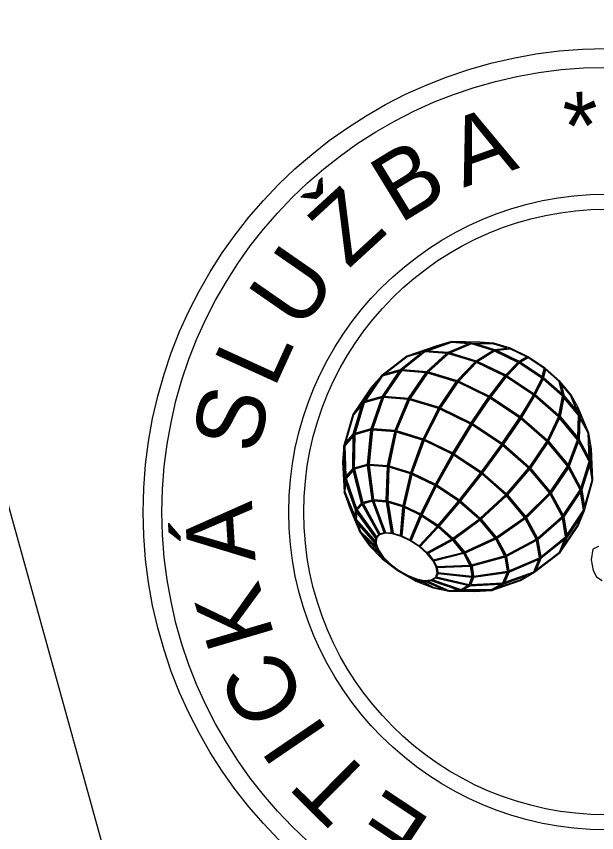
# Model space of a CAD drawing. Extents: x -821172 to -820632, y -1070921 to -1069931.
# Drawn here: x -820939.57 to -820934.74, y -1069983.01 to -1069976.22 of the extents above; entities that cross this region are included whole.
import ezdxf

# ---------------------------------------------------------------- set-up
doc = ezdxf.new("R2010")
doc.units = 0
doc.layers.add('Popisove_pole', color=7, linetype='Continuous')

msp = doc.modelspace()

# ---------------------------------------------------------------- linework, layer by layer
at = {"layer": 'Popisove_pole'}
for p, q in [((-820922.8738, -1070040.6021), (-820945.6304, -1069958.705)), ((-820936.0656, -1069978.9676), (-820936.3151, -1069979.0542)), ((-820936.5533, -1069980.6588), (-820936.7069, -1069980.5118)), ((-820936.5134, -1069980.717), (-820936.6302, -1069980.6233)), ((-820936.4561, -1069980.7752), (-820936.5203, -1069980.7351)), ((-820936.3865, -1069980.8284), (-820936.3868, -1069980.8372)), ((-820936.3109, -1069980.8718), (-820936.2417, -1069980.9205)), ((-820936.2359, -1069980.9016), (-820936.0978, -1069980.9776)), ((-820936.1683, -1069980.915), (-820935.968, -1069981.0034))]:
    msp.add_line(p, q, dxfattribs=at)
for points in [[(-820936.2417, -1069980.9205), (-820936.0978, -1069980.9776), (-820935.968, -1069981.0034), (-820935.755, -1069981.008), (-820935.6092, -1069980.9972), (-820935.371, -1069980.9153), (-820935.2541, -1069980.847), (-820935.0412, -1069980.6823), (-820934.8907, -1069980.4598), (-820934.8386, -1069980.3319), (-820934.7669, -1069980.0799), (-820934.7797, -1069979.8188), (-820934.8007, -1069979.6889), (-820934.8911, -1069979.4769), (-820934.9483, -1069979.3692), (-820935.0427, -1069979.2562), (-820935.1658, -1069979.1481), (-820935.3066, -1069979.0544), (-820935.4528, -1069978.9834), (-820935.5912, -1069978.9414), (-820935.7096, -1069978.9323), (-820935.9449, -1069978.9276), (-820936.0677, -1069978.9617), (-820936.3171, -1069979.0483), (-820936.5256, -1069979.2094), (-820936.6162, -1069979.3116), (-820936.7667, -1069979.5342), (-820936.8398, -1069979.7919), (-820936.8512, -1069979.9303), (-820936.839, -1069980.1789), (-820936.7879, -1069980.3207), (-820936.7069, -1069980.5118), (-820936.6302, -1069980.6233), (-820936.5203, -1069980.7351), (-820936.3868, -1069980.8372)], [(-820935.944, -1069978.9339), (-820936.1395, -1069979.0033), (-820935.9711, -1069979.0163), (-820935.8051, -1069978.9447)], [(-820935.779, -1069978.9471), (-820935.9519, -1069979.0216), (-820935.7381, -1069979.0864), (-820935.6009, -1069979.001)], [(-820935.5921, -1069978.9477), (-820935.7364, -1069978.9469), (-820935.5853, -1069978.9927), (-820935.4832, -1069978.9807)], [(-820935.5639, -1069979.0028), (-820935.3819, -1069979.0912), (-820935.3199, -1069979.0549), (-820935.4538, -1069978.9898)], [(-820936.4965, -1069979.1948), (-820936.3676, -1069979.159), (-820936.1968, -1069979.0213), (-820936.3143, -1069979.054)], [(-820936.1673, -1069979.0136), (-820936.3485, -1069979.1597), (-820936.1501, -1069979.175), (-820935.9852, -1069979.0278)], [(-820935.9685, -1069979.0297), (-820936.1354, -1069979.1787), (-820935.8964, -1069979.2512), (-820935.7487, -1069979.0963)], [(-820935.5855, -1069979.0062), (-820935.7243, -1069979.0926), (-820935.4927, -1069979.2051), (-820935.3921, -1069979.1002)], [(-820935.3068, -1069979.0617), (-820935.3698, -1069979.0986), (-820935.1887, -1069979.2191), (-820935.1728, -1069979.1509)], [(-820935.7358, -1069979.1008), (-820935.8841, -1069979.2564), (-820935.6288, -1069979.3804), (-820935.501, -1069979.2149)], [(-820935.3807, -1069979.1064), (-820935.4817, -1069979.2116), (-820935.2568, -1069979.3612), (-820935.1927, -1069979.2315)], [(-820936.6614, -1069979.4214), (-820936.5191, -1069979.3818), (-820936.3794, -1069979.1753), (-820936.5217, -1069979.2148)], [(-820936.504, -1069979.3818), (-820936.3016, -1069979.3975), (-820936.1591, -1069979.1869), (-820936.3615, -1069979.1712)], [(-820936.2885, -1069979.4005), (-820936.0476, -1069979.4735), (-820935.9044, -1069979.2618), (-820936.1453, -1069979.1888)], [(-820935.1621, -1069979.1597), (-820935.1778, -1069979.2271), (-820935.0234, -1069979.3627), (-820935.0483, -1069979.2596)], [(-820936.0358, -1069979.4784), (-820935.7796, -1069979.6028), (-820935.6362, -1069979.3907), (-820935.8924, -1069979.2663)], [(-820935.49, -1069979.2211), (-820935.6179, -1069979.3868), (-820935.371, -1069979.551), (-820935.2628, -1069979.3723)], [(-820935.1827, -1069979.2394), (-820935.2466, -1069979.3688), (-820935.0513, -1069979.5405), (-820935.0195, -1069979.3828)], [(-820936.7082, -1069979.4587), (-820936.681, -1069979.4281), (-820936.5841, -1069979.2849), (-820936.6113, -1069979.3155)], [(-820935.0303, -1069979.2808), (-820935.0069, -1069979.3776), (-820934.9011, -1069979.5042), (-820934.9538, -1069979.3724)], [(-820936.7472, -1069979.6889), (-820936.6135, -1069979.6517), (-820936.525, -1069979.3965), (-820936.6711, -1069979.437)], [(-820936.5109, -1069979.3938), (-820936.6001, -1069979.6512), (-820936.4135, -1069979.6657), (-820936.3075, -1069979.4096)], [(-820936.401, -1069979.6683), (-820936.1798, -1069979.7353), (-820936.0539, -1069979.4847), (-820936.2948, -1069979.4117)], [(-820935.7688, -1069979.6091), (-820935.5213, -1069979.7738), (-820935.3778, -1069979.5616), (-820935.6253, -1069979.3969)], [(-820935.2529, -1069979.38), (-820935.361, -1069979.5586), (-820935.1459, -1069979.7476), (-820935.0549, -1069979.5539)], [(-820935.0091, -1069979.3945), (-820935.0405, -1069979.5506), (-820934.8941, -1069979.7259), (-820934.8871, -1069979.5405)], [(-820936.8263, -1069979.7673), (-820936.7621, -1069979.6948), (-820936.6903, -1069979.4574), (-820936.7611, -1069979.5372)], [(-820934.8998, -1069979.4737), (-820934.8751, -1069979.5357), (-820934.8636, -1069979.5572), (-820934.8967, -1069979.4796)], [(-820936.1681, -1069979.74), (-820935.9331, -1069979.8542), (-820935.7864, -1069979.6134), (-820936.0422, -1069979.4891)], [(-820935.3679, -1069979.5692), (-820935.5113, -1069979.7813), (-820935.2955, -1069979.971), (-820935.152, -1069979.7589)], [(-820935.0458, -1069979.5638), (-820935.1364, -1069979.7569), (-820934.9731, -1069979.9523), (-820934.8956, -1069979.7436)], [(-820934.8754, -1069979.5618), (-820934.8822, -1069979.7409), (-820934.7994, -1069979.8966), (-820934.8069, -1069979.6906)], [(-820936.7539, -1069979.9775), (-820936.6433, -1069979.9468), (-820936.6158, -1069979.6653), (-820936.7503, -1069979.7027)], [(-820936.603, -1069979.6635), (-820936.6306, -1069979.9459), (-820936.4769, -1069979.9578), (-820936.417, -1069979.678)], [(-820936.4047, -1069979.6802), (-820936.4646, -1069979.9602), (-820936.2823, -1069980.0154), (-820936.1847, -1069979.7469)], [(-820935.7755, -1069979.6196), (-820935.9222, -1069979.8604), (-820935.6952, -1069980.0115), (-820935.5285, -1069979.784)], [(-820936.8239, -1069980.048), (-820936.7665, -1069979.9834), (-820936.763, -1069979.7146), (-820936.8335, -1069979.7941)], [(-820936.173, -1069979.7515), (-820936.2707, -1069980.02), (-820936.0768, -1069980.1141), (-820935.9393, -1069979.865)], [(-820935.5186, -1069979.7916), (-820935.6853, -1069980.0191), (-820935.4872, -1069980.1931), (-820935.303, -1069979.981)], [(-820935.1432, -1069979.7682), (-820935.2864, -1069979.98), (-820935.122, -1069980.1768), (-820934.9788, -1069979.965)], [(-820934.8875, -1069979.7576), (-820934.9642, -1069979.9641), (-820934.8677, -1069980.1456), (-820934.7989, -1069979.9242)], [(-820934.7908, -1069979.789), (-820934.786, -1069979.9229), (-820934.7786, -1069979.9684), (-820934.7859, -1069979.8194)], [(-820935.9285, -1069979.8713), (-820936.0659, -1069980.1203), (-820935.8786, -1069980.245), (-820935.7028, -1069980.0214)], [(-820936.8374, -1069980.0837), (-820936.8358, -1069980.0637), (-820936.8421, -1069979.896), (-820936.845, -1069979.9304)], [(-820934.7941, -1069979.9508), (-820934.8598, -1069980.1622), (-820934.8369, -1069980.3032), (-820934.7732, -1069980.0795)], [(-820936.7343, -1069980.3159), (-820936.694, -1069980.2705), (-820936.7634, -1069979.9987), (-820936.8224, -1069980.0652)], [(-820936.6827, -1069980.2645), (-820936.6062, -1069980.2432), (-820936.6427, -1069979.9596), (-820936.7527, -1069979.9902)], [(-820936.6303, -1069979.9585), (-820936.5937, -1069980.242), (-820936.4869, -1069980.2502), (-820936.4784, -1069979.9702)], [(-820936.4659, -1069979.9728), (-820936.4745, -1069980.2524), (-820936.3471, -1069980.291), (-820936.2859, -1069980.0274)], [(-820935.2943, -1069979.99), (-820935.4784, -1069980.202), (-820935.3274, -1069980.3827), (-820935.13, -1069980.1868)], [(-820934.9716, -1069979.9767), (-820935.1142, -1069980.1875), (-820935.016, -1069980.3722), (-820934.8735, -1069980.1614)], [(-820936.2741, -1069980.0322), (-820936.3353, -1069980.2955), (-820936.1992, -1069980.3616), (-820936.0826, -1069980.1252)], [(-820935.6929, -1069980.029), (-820935.8687, -1069980.2526), (-820935.7053, -1069980.3961), (-820935.4959, -1069980.2021)], [(-820936.7476, -1069980.384), (-820936.743, -1069980.3289), (-820936.8257, -1069980.0936), (-820936.8326, -1069980.1779)], [(-820936.0717, -1069980.1315), (-820936.1883, -1069980.3677), (-820936.0567, -1069980.4553), (-820935.8866, -1069980.2547)], [(-820935.4872, -1069980.211), (-820935.6966, -1069980.4051), (-820935.5722, -1069980.554), (-820935.337, -1069980.3907)], [(-820935.1231, -1069980.1975), (-820935.3202, -1069980.3931), (-820935.2297, -1069980.5633), (-820935.0245, -1069980.3829)], [(-820934.8698, -1069980.1783), (-820935.0101, -1069980.3858), (-820934.9855, -1069980.5379), (-820934.8452, -1069980.3304)], [(-820936.5683, -1069980.5531), (-820936.5506, -1069980.5331), (-820936.6884, -1069980.283), (-820936.7287, -1069980.3285)], [(-820936.6779, -1069980.2761), (-820936.5399, -1069980.5266), (-820936.5055, -1069980.5171), (-820936.6031, -1069980.2554)], [(-820936.59, -1069980.2548), (-820936.4928, -1069980.5153), (-820936.443, -1069980.5192), (-820936.4862, -1069980.2628)], [(-820936.473, -1069980.2659), (-820936.43, -1069980.5212), (-820936.369, -1069980.5397), (-820936.3491, -1069980.3034)], [(-820935.8766, -1069980.2623), (-820936.0467, -1069980.463), (-820935.9321, -1069980.5638), (-820935.7152, -1069980.4041)], [(-820936.737, -1069980.4082), (-820936.5774, -1069980.5907), (-820936.5753, -1069980.5649), (-820936.7319, -1069980.3456)], [(-820936.337, -1069980.3085), (-820936.3568, -1069980.5442), (-820936.2905, -1069980.5764), (-820936.2044, -1069980.3729)], [(-820936.1935, -1069980.3793), (-820936.2795, -1069980.5826), (-820936.2148, -1069980.6256), (-820936.0651, -1069980.4648)], [(-820935.7063, -1069980.413), (-820935.9234, -1069980.5729), (-820935.8363, -1069980.677), (-820935.5834, -1069980.5602)], [(-820935.3301, -1069980.4011), (-820935.5652, -1069980.5644), (-820935.4907, -1069980.7045), (-820935.24, -1069980.5706)], [(-820935.0211, -1069980.3965), (-820935.2248, -1069980.5756), (-820935.2018, -1069980.7179), (-820934.9959, -1069980.5518)], [(-820934.867, -1069980.3851), (-820934.9836, -1069980.5574), (-820935.0128, -1069980.6291), (-820934.8963, -1069980.4568)], [(-820936.5682, -1069980.6359), (-820936.5779, -1069980.6092), (-820936.7263, -1069980.4394), (-820936.7015, -1069980.5083)], [(-820936.2049, -1069980.6333), (-820936.1489, -1069980.6825), (-820935.9433, -1069980.5706), (-820936.055, -1069980.4723)], [(-820936.5425, -1069980.6856), (-820936.5581, -1069980.6629), (-820936.6673, -1069980.5583), (-820936.6256, -1069980.619)], [(-820936.1497, -1069980.6901), (-820936.2139, -1069980.6337), (-820936.2873, -1069980.5849), (-820936.3634, -1069980.5479), (-820936.4355, -1069980.526), (-820936.4972, -1069980.5213), (-820936.543, -1069980.534), (-820936.5688, -1069980.5631), (-820936.5724, -1069980.606), (-820936.5533, -1069980.6588), (-820936.5134, -1069980.717), (-820936.4561, -1069980.7752), (-820936.3865, -1069980.8284), (-820936.3109, -1069980.8718), (-820936.2359, -1069980.9016), (-820936.1683, -1069980.915), (-820936.1139, -1069980.911), (-820936.0777, -1069980.8899), (-820936.0629, -1069980.8535), (-820936.0707, -1069980.8051), (-820936.1006, -1069980.7489)], [(-820936.14, -1069980.6919), (-820936.0983, -1069980.742), (-820935.8493, -1069980.681), (-820935.9339, -1069980.5797)], [(-820935.8294, -1069980.6876), (-820935.7776, -1069980.7851), (-820935.5025, -1069980.709), (-820935.5761, -1069980.5706)], [(-820935.2363, -1069980.5828), (-820935.4864, -1069980.7164), (-820935.4674, -1069980.834), (-820935.2132, -1069980.7256)], [(-820935.0041, -1069980.5745), (-820935.201, -1069980.7333), (-820935.2395, -1069980.8278), (-820935.0464, -1069980.6784)], [(-820936.5164, -1069980.7302), (-820936.4976, -1069980.7419), (-820936.5176, -1069980.7216), (-820936.5518, -1069980.6942)], [(-820935.8413, -1069980.6919), (-820936.0913, -1069980.7531), (-820936.0671, -1069980.7987), (-820935.791, -1069980.7866)], [(-820935.4984, -1069980.7208), (-820935.7737, -1069980.7969), (-820935.7606, -1069980.8782), (-820935.4794, -1069980.8376)], [(-820935.2177, -1069980.7412), (-820935.4674, -1069980.8476), (-820935.501, -1069980.9298), (-820935.2588, -1069980.8421)], [(-820936.3871, -1069980.8291), (-820936.3927, -1069980.8249)], [(-820936.0634, -1069980.811), (-820936.0575, -1069980.8478), (-820935.7732, -1069980.8782), (-820935.7861, -1069980.7989)], [(-820936.3708, -1069980.8392), (-820936.3564, -1069980.8475)], [(-820936.1881, -1069980.9351), (-820936.2386, -1069980.9072), (-820936.2641, -1069980.8971), (-820936.2387, -1069980.915)], [(-820935.811, -1069980.9577), (-820936.0767, -1069980.8965), (-820936.0989, -1069980.9095), (-820935.8644, -1069980.9889)], [(-820935.7747, -1069980.8906), (-820936.0589, -1069980.8602), (-820936.0692, -1069980.8854), (-820935.798, -1069980.9479)], [(-820935.4822, -1069980.8506), (-820935.7613, -1069980.891), (-820935.7847, -1069980.9484), (-820935.5164, -1069980.9344)], [(-820935.3167, -1069980.8763), (-820935.5094, -1069980.9461), (-820935.5515, -1069980.9707), (-820935.3736, -1069980.9095)], [(-820936.0225, -1069980.9862), (-820936.1702, -1069980.921), (-820936.1975, -1069980.9156), (-820936.0957, -1069980.9717)], [(-820935.8949, -1069980.9918), (-820936.1147, -1069980.9174), (-820936.1428, -1069980.9194), (-820935.9669, -1069980.9971)], [(-820935.5374, -1069980.948), (-820935.7924, -1069980.9613), (-820935.8408, -1069980.9896), (-820935.6108, -1069980.9909)]]:
    msp.add_lwpolyline(points, close=True, dxfattribs=at)
for points in [[(-820936.4972, -1069980.5213), (-820936.5993, -1069980.2478), (-820936.6375, -1069979.9517), (-820936.6086, -1069979.6568), (-820936.5152, -1069979.3872), (-820936.3647, -1069979.1647), (-820936.1693, -1069979.0072), (-820935.9449, -1069978.9276)], [(-820934.8007, -1069979.6889), (-820934.8808, -1069979.5383), (-820935.0127, -1069979.3805), (-820935.1847, -1069979.2293), (-820935.3816, -1069979.0983), (-820935.5859, -1069978.9991), (-820935.7794, -1069978.9404), (-820935.9449, -1069978.9276)], [(-820936.4355, -1069980.526), (-820936.4809, -1069980.257), (-820936.4719, -1069979.9645), (-820936.4094, -1069979.6723), (-820936.2984, -1069979.404), (-820936.1479, -1069979.1815), (-820935.9701, -1069979.0227), (-820935.7794, -1069978.9404), (-820935.5912, -1069978.9414)], [(-820936.3634, -1069980.5479), (-820936.3425, -1069980.2989), (-820936.2785, -1069980.0231), (-820936.1766, -1069979.7428), (-820936.045, -1069979.4808), (-820935.8945, -1069979.2583), (-820935.7372, -1069979.0932), (-820935.5859, -1069978.9991), (-820935.4528, -1069978.9834)], [(-820934.7669, -1069980.0799), (-820934.7922, -1069979.9235), (-820934.8885, -1069979.7423), (-820935.0473, -1069979.5523), (-820935.2543, -1069979.3704), (-820935.4913, -1069979.2127), (-820935.7372, -1069979.0932), (-820935.9701, -1069979.0227), (-820936.1693, -1069979.0072), (-820936.3171, -1069979.0483)], [(-820936.2873, -1069980.5849), (-820936.1963, -1069980.3699), (-820936.0742, -1069980.1223), (-820935.9307, -1069979.8623), (-820935.7775, -1069979.6108), (-820935.627, -1069979.3883), (-820935.4913, -1069979.2127), (-820935.3816, -1069979.0983), (-820935.3066, -1069979.0544)], [(-820934.8386, -1069980.3319), (-820934.8662, -1069980.1618), (-820934.971, -1069979.9646), (-820935.1437, -1069979.7578), (-820935.3691, -1069979.5599), (-820935.627, -1069979.3883), (-820935.8945, -1069979.2583), (-820936.1479, -1069979.1815), (-820936.3647, -1069979.1647), (-820936.5256, -1069979.2094)], [(-820936.2139, -1069980.6337), (-820936.0555, -1069980.4636), (-820935.8773, -1069980.2534), (-820935.6937, -1069980.02), (-820935.5196, -1069979.7824), (-820935.3691, -1069979.5599), (-820935.2543, -1069979.3704), (-820935.1847, -1069979.2293), (-820935.1658, -1069979.1481)], [(-820936.543, -1069980.534), (-820936.6872, -1069980.2722), (-820936.7603, -1069979.9858), (-820936.7565, -1069979.6979), (-820936.6761, -1069979.4319), (-820936.5256, -1069979.2094)], [(-820936.1497, -1069980.6901), (-820935.9324, -1069980.5718), (-820935.7052, -1069980.4045), (-820935.4866, -1069980.2019), (-820935.2943, -1069979.9804), (-820935.1437, -1069979.7578), (-820935.0473, -1069979.5523), (-820935.0127, -1069979.3805), (-820935.0427, -1069979.2562)], [(-820935.0412, -1069980.6823), (-820934.9891, -1069980.5544), (-820935.0167, -1069980.3843), (-820935.1215, -1069980.1872), (-820935.2943, -1069979.9804), (-820935.5196, -1069979.7824), (-820935.7775, -1069979.6108), (-820936.045, -1069979.4808), (-820936.2984, -1069979.404), (-820936.5152, -1069979.3872), (-820936.6761, -1069979.4319), (-820936.7667, -1069979.5342)], [(-820936.1006, -1069980.7489), (-820935.8381, -1069980.6847), (-820935.5733, -1069980.5624), (-820935.3279, -1069980.392), (-820935.1215, -1069980.1872), (-820934.971, -1069979.9646), (-820934.8885, -1069979.7423), (-820934.8808, -1069979.5383), (-820934.9483, -1069979.3692)], [(-820935.2541, -1069980.847), (-820935.2062, -1069980.7295), (-820935.2315, -1069980.5732), (-820935.3279, -1069980.392), (-820935.4866, -1069980.2019), (-820935.6937, -1069980.02), (-820935.9307, -1069979.8623), (-820936.1766, -1069979.7428), (-820936.4094, -1069979.6723), (-820936.6086, -1069979.6568), (-820936.7565, -1069979.6979), (-820936.8398, -1069979.7919)], [(-820936.0707, -1069980.8051), (-820935.7808, -1069980.7924), (-820935.4933, -1069980.713), (-820935.2315, -1069980.5732), (-820935.0167, -1069980.3843), (-820934.8662, -1069980.1618), (-820934.7922, -1069979.9235), (-820934.8007, -1069979.6889)], [(-820936.5688, -1069980.5631), (-820936.7367, -1069980.328), (-820936.8295, -1069980.0638), (-820936.8398, -1069979.7919)], [(-820935.6092, -1069980.9972), (-820935.5121, -1069980.9405), (-820935.4723, -1069980.8428), (-820935.4933, -1069980.713), (-820935.5733, -1069980.5624), (-820935.7052, -1069980.4045), (-820935.8773, -1069980.2534), (-820936.0742, -1069980.1223), (-820936.2785, -1069980.0231), (-820936.4719, -1069979.9645), (-820936.6375, -1069979.9517), (-820936.7603, -1069979.9858), (-820936.8295, -1069980.0638), (-820936.839, -1069980.1789)], [(-820936.5724, -1069980.606), (-820936.7435, -1069980.4103), (-820936.839, -1069980.1789)], [(-820935.968, -1069981.0034), (-820935.8637, -1069980.9957), (-820935.7942, -1069980.9552), (-820935.7657, -1069980.8853), (-820935.7808, -1069980.7924), (-820935.8381, -1069980.6847), (-820935.9324, -1069980.5718), (-820936.0555, -1069980.4636), (-820936.1963, -1069980.3699), (-820936.3425, -1069980.2989), (-820936.4809, -1069980.257), (-820936.5993, -1069980.2478), (-820936.6872, -1069980.2722), (-820936.7367, -1069980.328), (-820936.7435, -1069980.4103), (-820936.7069, -1069980.5118)], [(-820936.0629, -1069980.8535), (-820935.7657, -1069980.8853), (-820935.4723, -1069980.8428), (-820935.2062, -1069980.7295), (-820934.9891, -1069980.5544), (-820934.8386, -1069980.3319)], [(-820934.7199, -1069980.6329), (-820934.7682, -1069980.6532), (-820934.7822, -1069980.7442), (-820934.7645, -1069980.8308), (-820934.7365, -1069980.8845), (-820934.6915, -1069980.9141)], [(-820936.0777, -1069980.8899), (-820935.7942, -1069980.9552), (-820935.5121, -1069980.9405), (-820935.2541, -1069980.847)], [(-820936.1139, -1069980.911), (-820935.8637, -1069980.9957), (-820935.6092, -1069980.9972)]]:
    msp.add_lwpolyline(points, dxfattribs=at)
for radius in [3.8563, 3.7, 3.7, 2.6447, 2.6447, 2.5197]:
    msp.add_circle((-820934.6544, -1069980.3456), radius, dxfattribs=at)

# ---------------------------------------------------------------- texts
for s, rotation, p in [('*', 2.51854, (-820935.0021, -1069977.4177)), ('A', 19.54539, (-820935.8442, -1069977.6479)), ('B', 31.4663, (-820936.3758, -1069977.9518)), ('Ž', 42.5327, (-820936.8033, -1069978.3268)), ('U', 55.29757, (-820937.1962, -1069978.8515)), ('L', 65.52001, (-820937.4211, -1069979.3263)), ('S', 76.58641, (-820937.5653, -1069979.8763)), ('Á', 93.61327, (-820937.5751, -1069980.7492)), ('K', 106.37813, (-820937.4138, -1069981.3846)), ('C', 118.29904, (-820937.1396, -1069981.9321)), ('I', 124.25949, (-820936.9615, -1069982.1816)), ('T', 135.3259, (-820936.5661, -1069982.5903)), ('E', 146.3923, (-820936.0997, -1069982.9155))]:
    msp.add_text(s, height=0.5625, rotation=rotation, dxfattribs=at).set_placement(p)

doc.saveas('drawing.dxf')
